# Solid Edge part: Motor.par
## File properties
Author: CADCIM
Template: NORMENG.PAR
Last saved by: TIET
Revision: 8
Application: Solid Edge
Accuracy: 0.99
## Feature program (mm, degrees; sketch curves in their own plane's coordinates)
sketch for "unnamed Protrusion 1" plane through (0, 0, 0) normal (0, -1, 0) x-axis (1, 0, 0)
  line (-152.4, 0) -> (152.4, 0)
  line (152.4, 0) -> (83.1942, 183.7359)
  line (-152.4, 0) -> (-83.1942, 183.7359)
  dimension (linear) = 152.4
extrude "unnamed Protrusion 1" add finite 165.1 along -normal
sketch for "ExtrudedProtrusion_2" plane through (0, 165.1, 120.65) normal (0, 1, 0) x-axis (-1, 0, 0)
  circle centre (0, 31.75) radius 88.9
extrude "ExtrudedProtrusion_2" add finite 57.15 along +normal
sketch for "ExtrudedProtrusion_3" plane through (0, 222.25, 152.4) normal (0, 1, 0) x-axis (-1, 0, 0)
  circle centre (0, 0) radius 127
extrude "ExtrudedProtrusion_3" add finite 12.7 along +normal
sketch for "ExtrudedProtrusion_4" plane through (0, 222.25, 152.4) normal (0, -1, 0) x-axis (1, 0, 0)
  line (-76.2, 25.4) -> (76.2, 25.4)
  line (76.2, 25.4) -> (76.2, 152.4)
  line (76.2, 152.4) -> (-76.2, 152.4)
  line (-76.2, 152.4) -> (-76.2, 25.4)
  dimension (linear) = 76.2
  dimension (linear) = 76.2
extrude "ExtrudedProtrusion_4" add finite 203.2 along +normal
sketch for "unnamed Cutout 1" plane through (0, 19.05, 251.4953) normal (0, -1, 0) x-axis (1, 0, 0)
  line (-76.2, 41.8747) -> (-63.5, 41.8747)
  line (-63.5, 41.8747) -> (-63.5, 30.4447)
  line (-63.5, 30.4447) -> (-76.2, 30.4447)
  line (-76.2, 30.4447) -> (-76.2, 41.8747)
  dimension (linear) = 76.2
  dimension (linear) = 76.2
  dimension (linear) = 63.5
extrude "unnamed Cutout 1" cut along +normal
pattern "unnamed Pattern 1" of "unnamed Cutout 1"
extrude "unnamed Cutout 2" cut
extrude "unnamed Cutout 3" cut
extrude "unnamed Cutout 4" cut
extrude "unnamed Cutout 5" cut
extrude "unnamed Cutout 6" cut
extrude "unnamed Cutout 7" cut
extrude "unnamed Cutout 8" cut
sketch for "Hole_1" plane through (0, 234.95, 152.4) normal (0, 1, 0) x-axis (-1, 0, 0)
  hole centre (0, 0) bore radius 76.2
hole "Hole_1" diameter 152.4 finite
sketch for "Hole_2" plane through (0, 0, 120.65) normal (0, -1, 0) x-axis (1, 0, 0)
  hole centre (0, 31.75) bore radius 19.05
hole "Hole_2" diameter 38.1 through
sketch for "Hole_3" plane through (0, 234.95, 152.4) normal (0, 1, 0) x-axis (-1, 0, 0)
  hole centre (0, -107.95) bore radius 9.525
hole "Hole_3" diameter 19.05 through
pattern "unnamed Pattern 2" of "Hole_3"
pattern "unnamed Pattern 3"
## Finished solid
Body 1: solid body, 60 faces, 151 edges, 90 vertices.
  Faces by surface: plane 53, cylinder 7
  Edges by curve: line 126, circle 25
Bounding box of the edges (mm): 304.800 x 234.950 x 304.800, from (-152.4, 0, 0) to (152.4, 234.95, 304.8).
Cylindrical faces by radius (mm): R9.525 x3, R19.05 x1, R76.2 x1, R88.9 x1, R127 x1
Planar faces by outward normal: +x 9, +y 8, +z 9, -x 9, -y 7, -z 9, oblique 2
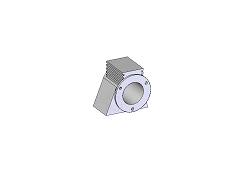
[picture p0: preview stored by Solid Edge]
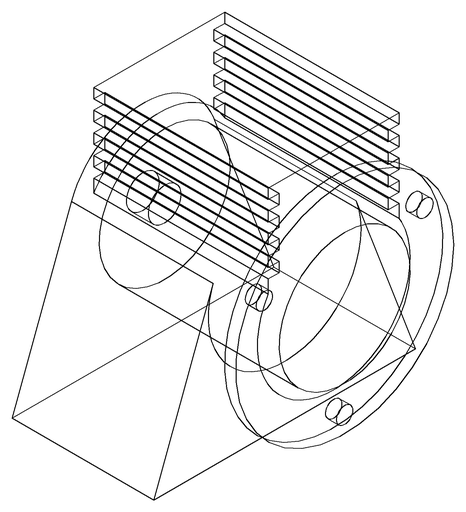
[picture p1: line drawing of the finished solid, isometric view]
